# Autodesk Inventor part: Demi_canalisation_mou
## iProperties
Shininess: 64.0
Length Units: 11269
Angle Units: 11279
Time Units: 11290
Mass Units: 11283
Length Display Precision: 3
Angle Display Precision: 2
Compacted: True
Part Number: Demi_canalisation_mou
Document SubType Name: Sheet Metal
Created: 2008-02
Material: Acier inoxydable, austénitique
Designer: Pascal
Density: 8.03 g/cm^3
Density: 0.0
Volumn: 0.0
Area: 0.0
PropertySet Name: Model Information
Control State: 0
Master: False
Checked Out: False
Author: Pascal
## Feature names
1. Plaque1
2. Pli1
3. Plaque2
4. Pli2
5. Plaque3
6. Pli3
7. Ouverture1
